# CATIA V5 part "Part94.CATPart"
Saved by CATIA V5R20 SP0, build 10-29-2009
Part number: FA 063200-3
Revision: ANY
Definition: UNKNOWN
Nomenclature: FA 063200-3
Source: Unknown
Bounding box of the stored display mesh (mm): x -2.109 to 2.109, y -2.45 to 2.45, z -2 to 2
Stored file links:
  C:\Users\Utente\Desktop\IO LAVORO\3D X SITO CF\CUMSA\3D files FA\FA 063200\Part94.CATPart

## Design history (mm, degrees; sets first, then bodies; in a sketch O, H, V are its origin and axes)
Body1 "Chaflán4" (main body)
  Solid1: solid without history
